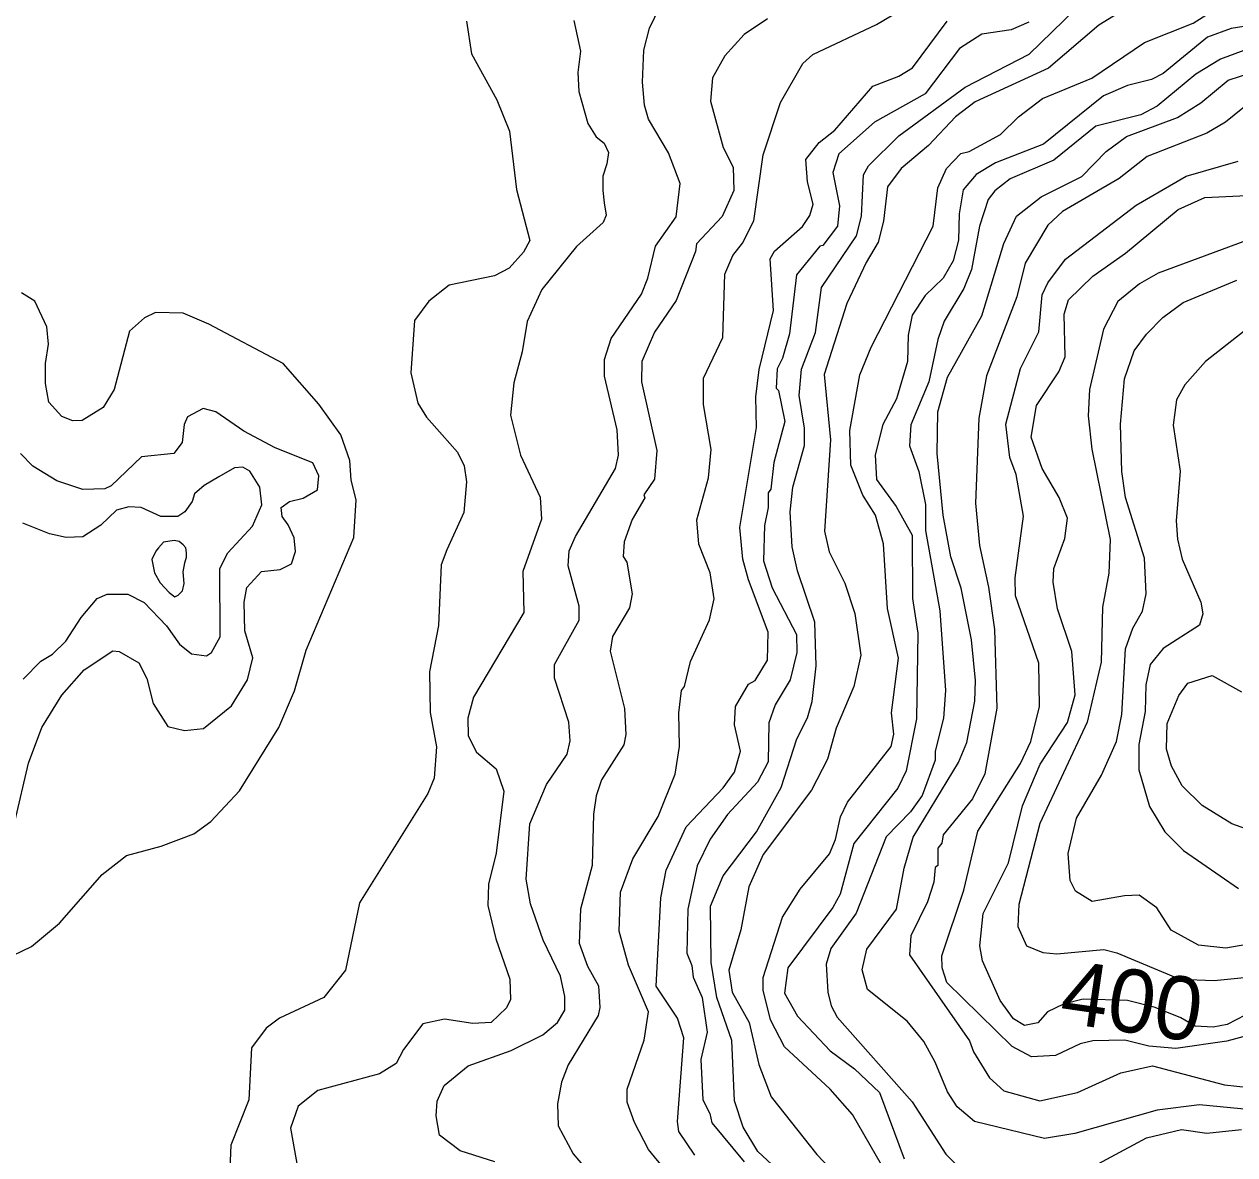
# Model space of a CAD drawing. Extents: x 673.6 to 698.9, y 7012 to 7040.1.
# Drawn here: x 675.042 to 676.578, y 7037.51 to 7038.944 of the extents above; entities that cross this region are included whole.
import ezdxf
from ezdxf.enums import TextEntityAlignment as Align

# ---------------------------------------------------------------- set-up
doc = ezdxf.new("R2010")
doc.units = 0
doc.header["$LTSCALE"] = 0.032
doc.layers.add('1', color=7, linetype='Continuous', lineweight=25)
doc.layers.add('2', color=7, linetype='Continuous', lineweight=13)
doc.layers.add('61', color=7, linetype='Continuous')

msp = doc.modelspace()

# ---------------------------------------------------------------- linework, layer by layer
at = {"layer": '1'}
for points in [[(675.6031, 7038.9478), (675.6096, 7038.9062), (675.6418, 7038.848), (675.6579, 7038.8082), (675.6666, 7038.7342), (675.6836, 7038.6694), (675.6755, 7038.6545), (675.6571, 7038.6346), (675.6388, 7038.6248), (675.581, 7038.6129), (675.5554, 7038.5927), (675.5373, 7038.5678), (675.5324, 7038.5016), (675.5413, 7038.463), (675.5525, 7038.4452), (675.5721, 7038.4231), (675.5917, 7038.401), (675.6003, 7038.3836), (675.603, 7038.3635), (675.5999, 7038.3245), (675.578, 7038.2772), (675.5709, 7038.2579), (675.5676, 7038.181), (675.5562, 7038.1223), (675.5569, 7038.0706), (675.5652, 7038.027), (675.5619, 7037.9875), (675.5539, 7037.9678), (675.4675, 7037.8293), (675.4496, 7037.744), (675.4219, 7037.7093), (675.366, 7037.6828), (675.3488, 7037.6704), (675.3304, 7037.6455), (675.3269, 7037.5795), (675.3039, 7037.522), (675.3023, 7037.4821)], [(675.8563, 7037.8708), (675.882, 7037.9256), (675.9287, 7037.9751), (675.9433, 7037.9949), (675.9506, 7038.0217), (675.9432, 7038.0549), (675.9443, 7038.0785), (675.961, 7038.1067), (675.9695, 7038.1112), (675.9851, 7038.1371), (675.9859, 7038.1728), (675.9609, 7038.2389), (675.9539, 7038.2653), (675.9498, 7038.3052), (675.9711, 7038.4321), (675.9704, 7038.4712), (675.9743, 7038.5057), (675.9925, 7038.5805), (675.9883, 7038.6463), (675.994, 7038.6559), (676.0295, 7038.6873), (676.0388, 7038.7012), (676.0432, 7038.7156), (676.0359, 7038.7439), (676.0339, 7038.7721), (676.0506, 7038.7938), (676.0703, 7038.8095), (676.1188, 7038.8654), (676.1516, 7038.8778), (676.1691, 7038.8886), (676.2131, 7038.9479)], [(676.6055, 7038.9436), (676.5735, 7038.9385), (676.5434, 7038.9274), (676.4872, 7038.8812), (676.4725, 7038.8736), (676.442, 7038.8662), (676.4116, 7038.8532), (676.3351, 7038.7917), (676.2743, 7038.7682), (676.25, 7038.7533), (676.2333, 7038.7337), (676.2283, 7038.7034), (676.2274, 7038.67), (676.2208, 7038.6438), (676.208, 7038.6219), (676.1851, 7038.5996), (676.1685, 7038.5746), (676.1635, 7038.5496), (676.1625, 7038.516), (676.1486, 7038.4688), (676.1315, 7038.4361), (676.1215, 7038.3977), (676.1234, 7038.3664), (676.1484, 7038.3321), (676.1685, 7038.2955), (676.1692, 7038.2152), (676.1758, 7038.1712), (676.1741, 7038.0628), (676.1609, 7037.9967), (676.1506, 7037.9748), (676.0946, 7037.9044), (676.0774, 7037.8401), (676.0681, 7037.8233), (676.0109, 7037.7468), (676.0066, 7037.7147), (676.0232, 7037.6855), (676.0646, 7037.6414), (676.0955, 7037.6187), (676.1271, 7037.5885), (676.1584, 7037.5043)], [(676.6139, 7037.6987), (676.5685, 7037.6751), (676.5506, 7037.6717), (676.5276, 7037.6728), (676.5094, 7037.6833), (676.4771, 7037.6965), (676.442, 7037.7054), (676.3857, 7037.7072), (676.3607, 7037.7008), (676.3402, 7037.6912), (676.328, 7037.6769), (676.3112, 7037.6735), (676.297, 7037.682), (676.2805, 7037.7052), (676.2577, 7037.7556), (676.2547, 7037.7748), (676.2588, 7037.8159), (676.2907, 7037.88), (676.3086, 7037.9524), (676.3311, 7038.0052), (676.3658, 7038.0582), (676.3753, 7038.0931), (676.3714, 7038.1479), (676.3532, 7038.2024), (676.3476, 7038.2361), (676.3483, 7038.2534), (676.3624, 7038.2916), (676.3656, 7038.3171), (676.3551, 7038.3434), (676.3334, 7038.3803), (676.3196, 7038.4202), (676.3265, 7038.4602), (676.3547, 7038.5028), (676.3628, 7038.5221), (676.3615, 7038.5759), (676.3671, 7038.5943), (676.3977, 7038.6242), (676.4395, 7038.6535), (676.5061, 7038.709), (676.5401, 7038.7242), (676.6463, 7038.7291)], [(675.0282, 7037.7629), (675.0511, 7037.7737), (675.0866, 7037.8034), (675.141, 7037.8652), (675.1716, 7037.8893), (675.2155, 7037.901), (675.2571, 7037.9169), (675.2787, 7037.9323), (675.3152, 7037.9712), (675.3649, 7038.0516), (675.3849, 7038.098), (675.3996, 7038.1496), (675.46, 7038.2929), (675.4633, 7038.3405), (675.4567, 7038.3655), (675.455, 7038.3902), (675.4436, 7038.4231), (675.4159, 7038.4618), (675.3706, 7038.5136), (675.2763, 7038.5634), (675.2438, 7038.5772), (675.2085, 7038.578), (675.1947, 7038.5716), (675.1757, 7038.5545), (675.1559, 7038.4803), (675.1422, 7038.4576), (675.1153, 7038.441), (675.1037, 7038.4408), (675.0896, 7038.4463), (675.073, 7038.4642), (675.0689, 7038.488), (675.0689, 7038.5134), (675.0729, 7038.5381), (675.0706, 7038.5598), (675.0556, 7038.5927), (675.0384, 7038.6033)], [(675.871, 7037.552), (675.8791, 7037.658), (675.8708, 7037.6831), (675.8438, 7037.7235), (675.8497, 7037.8358), (675.8563, 7037.8708)], [(675.8929, 7037.5092), (675.8724, 7037.5392), (675.871, 7037.552)]]:
    msp.add_lwpolyline(points, dxfattribs=at)
at = {"layer": '2'}
for points in [[(675.9038, 7038.4614), (675.9038, 7038.4947), (675.9284, 7038.5463), (675.9309, 7038.6267), (675.9412, 7038.6505), (675.9532, 7038.6662), (675.9678, 7038.6943), (675.9796, 7038.7783), (676.0015, 7038.8446), (676.03, 7038.894), (676.0425, 7038.9054), (676.1235, 7038.9433), (676.1554, 7038.9627), (676.1834, 7038.9874), (676.2196, 7039.0277), (676.2547, 7039.0511), (676.2916, 7039.0808), (676.3678, 7039.1652), (676.4349, 7039.2174), (676.5299, 7039.2798), (676.5444, 7039.2961), (676.5523, 7039.33), (676.5579, 7039.4265), (676.581, 7039.4883)], [(676.2123, 7038.7607), (676.2304, 7038.7797), (676.2408, 7038.7822), (676.2808, 7038.804), (676.3034, 7038.8264), (676.3342, 7038.8498), (676.3965, 7038.8753), (676.4633, 7038.9206), (676.525, 7038.9454), (676.5585, 7038.9663), (676.6134, 7039.0256)], [(676.5151, 7039.0105), (676.4053, 7038.9425), (676.3416, 7038.8882), (676.2486, 7038.8456), (676.2237, 7038.8264), (676.1892, 7038.7902), (676.1547, 7038.7607), (676.1374, 7038.7376), (676.1323, 7038.6942), (676.1255, 7038.6672), (676.1102, 7038.6417), (676.0859, 7038.5896), (676.057, 7038.4995), (676.0649, 7038.4167), (676.0575, 7038.3007), (676.0634, 7038.2744), (676.0832, 7038.2346), (676.0959, 7038.1962), (676.1033, 7038.1433), (676.0944, 7038.1038), (676.0721, 7038.0509), (676.0614, 7038.0115), (676.0408, 7037.972), (675.9797, 7037.8905), (675.9615, 7037.8494), (675.9511, 7037.7952), (675.9359, 7037.744), (675.9403, 7037.7159), (675.9616, 7037.6774), (675.974, 7037.6242), (675.9896, 7037.5832), (676.0477, 7037.51), (676.1094, 7037.4453)], [(675.8332, 7038.6218), (675.8428, 7038.6623), (675.869, 7038.6997), (675.8742, 7038.742), (675.8594, 7038.7806), (675.8339, 7038.8236), (675.8291, 7038.8411), (675.8265, 7038.8705), (675.8282, 7038.9108), (675.8353, 7038.9387), (675.8561, 7038.982)], [(676.0079, 7037.4812), (675.9729, 7037.514), (675.954, 7037.5447), (675.9432, 7037.5779), (675.94, 7037.6548), (675.9207, 7037.7091), (675.9137, 7037.7534), (675.9129, 7037.8249), (675.929, 7037.8637), (675.9713, 7037.9193), (676.0024, 7037.9756), (676.0223, 7038.0375), (676.0359, 7038.0641), (676.0419, 7038.0845), (676.0467, 7038.1298), (676.0452, 7038.1852), (676.0233, 7038.2505), (676.0164, 7038.281), (676.014, 7038.3252), (676.0171, 7038.3566), (676.0319, 7038.4096), (676.0319, 7038.4313), (676.0254, 7038.4729), (676.0283, 7038.5062), (676.0459, 7038.5526), (676.0537, 7038.6097), (676.0978, 7038.6753), (676.1043, 7038.7005), (676.1067, 7038.7527), (676.1132, 7038.7644), (676.1519, 7038.8022), (676.2357, 7038.8639), (676.317, 7038.9057), (676.3757, 7038.9628)], [(675.7395, 7038.9487), (675.7476, 7038.9095), (675.7444, 7038.8828), (675.7456, 7038.8586), (675.7572, 7038.8179), (675.7676, 7038.8012), (675.778, 7038.7928), (675.7833, 7038.7813), (675.7812, 7038.7666), (675.776, 7038.7509), (675.776, 7038.7331), (675.778, 7038.7174), (675.7805, 7038.7016), (675.7766, 7038.6925), (675.7426, 7038.6617), (675.6988, 7038.6074), (675.68, 7038.5666), (675.6738, 7038.5282), (675.663, 7038.4888), (675.659, 7038.4481), (675.6718, 7038.3971), (675.6967, 7038.3437), (675.6983, 7038.3159), (675.6745, 7038.2498), (675.676, 7038.1977), (675.6119, 7038.0903), (675.6047, 7038.0635), (675.6051, 7038.0413), (675.6159, 7038.0202), (675.6406, 7037.9992), (675.6506, 7037.9708), (675.6409, 7037.8922), (675.6311, 7037.8531), (675.6302, 7037.8257), (675.6403, 7037.7837), (675.658, 7037.7324), (675.6589, 7037.7065), (675.654, 7037.696), (675.6346, 7037.6773), (675.611, 7037.6764), (675.5752, 7037.6815), (675.5476, 7037.6756), (675.5233, 7037.6433), (675.514, 7037.6256), (675.4926, 7037.6123), (675.4144, 7037.5912), (675.3894, 7037.5714), (675.3796, 7037.5434), (675.3892, 7037.4912)], [(675.9852, 7038.9507), (675.9553, 7038.931), (675.9311, 7038.9036), (675.9153, 7038.8758), (675.9129, 7038.8461), (675.9286, 7038.7873), (675.9414, 7038.7626), (675.9424, 7038.7328), (675.9275, 7038.7), (675.895, 7038.6653), (675.8938, 7038.6556), (675.869, 7038.5932), (675.8417, 7038.5532), (675.8257, 7038.516), (675.825, 7038.4901), (675.8446, 7038.4032)], [(676.3167, 7038.9463), (676.2942, 7038.9369), (676.2569, 7038.9314), (676.2287, 7038.9132), (676.1853, 7038.8555), (676.121, 7038.8197), (676.0755, 7038.7793), (676.0681, 7038.7559), (676.0763, 7038.7135), (676.0738, 7038.6877), (676.0553, 7038.6631), (676.0513, 7038.6622), (676.022, 7038.6261), (676.0128, 7038.5513), (676.0043, 7038.5203), (675.9973, 7038.5068), (675.9959, 7038.4821), (675.9991, 7038.479), (676.0072, 7038.44), (675.9933, 7038.3878), (675.9892, 7038.354), (675.986, 7038.3492), (675.9859, 7038.3307), (675.9811, 7038.308), (675.9802, 7038.2632), (675.9908, 7038.2287), (676.0219, 7038.1698), (676.0222, 7038.1469), (676.0139, 7038.1121), (675.9949, 7038.0805), (675.9867, 7038.0575), (675.9859, 7038.008), (675.9722, 7037.9825), (675.9344, 7037.9413), (675.9122, 7037.9102), (675.8958, 7037.876), (675.8841, 7037.8211), (675.8825, 7037.7656), (675.8891, 7037.7497), (675.8907, 7037.735), (675.9021, 7037.7091), (675.9087, 7037.6651), (675.9006, 7037.6305), (675.903, 7037.5792), (675.912, 7037.5619), (675.9144, 7037.5503), (675.9553, 7037.5009)], [(676.6451, 7038.9314), (676.56, 7038.8995), (676.5285, 7038.8803), (676.4796, 7038.8397), (676.4587, 7038.829), (676.4015, 7038.8144), (676.3482, 7038.7714), (676.2931, 7038.7478), (676.2737, 7038.7325), (676.2651, 7038.7217), (676.2539, 7038.6876), (676.2438, 7038.6327), (676.2343, 7038.6088), (676.2093, 7038.567), (676.2012, 7038.544), (676.1897, 7038.49), (676.1668, 7038.4358), (676.1652, 7038.409), (676.177, 7038.3766), (676.1855, 7038.3347), (676.1856, 7038.3014), (676.2036, 7038.1999), (676.2111, 7038.0986), (676.2085, 7038.0637), (676.198, 7038.0216), (676.1979, 7038.0102), (676.1813, 7037.9654), (676.1664, 7037.9449), (676.1357, 7037.9132), (676.0977, 7037.8162), (676.0655, 7037.7715), (676.0594, 7037.7516), (676.0616, 7037.716), (676.0658, 7037.6987), (676.0735, 7037.6841), (676.1686, 7037.5769), (676.2114, 7037.5103), (676.2265, 7037.4951)], [(676.6121, 7037.5655), (676.5332, 7037.5729), (676.4793, 7037.5661), (676.3751, 7037.5368), (676.3364, 7037.5303), (676.2479, 7037.5518), (676.2259, 7037.5706), (676.2134, 7037.5897), (676.1979, 7037.6272), (676.1833, 7037.6532), (676.1624, 7037.6792), (676.1118, 7037.7193), (676.1051, 7037.7444), (676.1109, 7037.7707), (676.1486, 7037.8212), (676.1585, 7037.8734), (676.1698, 7037.9124), (676.2276, 7038.0072), (676.2378, 7038.0328), (676.2481, 7038.0849), (676.2489, 7038.1112), (676.2439, 7038.163), (676.2308, 7038.2284), (676.2177, 7038.2682), (676.2078, 7038.3211), (676.2005, 7038.3993), (676.2013, 7038.4522), (676.2133, 7038.4963), (676.2571, 7038.5739), (676.2849, 7038.6656), (676.301, 7038.7005), (676.3324, 7038.7248), (676.384, 7038.7508), (676.415, 7038.7826), (676.4407, 7038.8013), (676.5055, 7038.8254), (676.5349, 7038.8441), (676.5698, 7038.8731), (676.648, 7038.8983)], [(676.6082, 7038.8536), (676.5661, 7038.8194), (676.5425, 7038.8058), (676.4669, 7038.7762), (676.4313, 7038.748), (676.3593, 7038.7063), (676.3409, 7038.6888), (676.3121, 7038.6408), (676.3014, 7038.5982), (676.2631, 7038.4977), (676.2531, 7038.444), (676.249, 7038.3361), (676.2539, 7038.2826), (676.2654, 7038.2296), (676.2729, 7038.1762), (676.2761, 7038.0763), (676.2609, 7037.9931), (676.245, 7037.9611), (676.208, 7037.9155), (676.2063, 7037.9049), (676.2013, 7037.8986), (676.2012, 7037.8768), (676.198, 7037.8743), (676.1962, 7037.8553), (676.188, 7037.8307), (676.167, 7037.7873), (676.1652, 7037.7631), (676.2415, 7037.6543), (676.2464, 7037.6404), (676.2666, 7037.6072), (676.2851, 7037.5907), (676.3308, 7037.578), (676.3783, 7037.5885), (676.4336, 7037.6136), (676.4735, 7037.6223), (676.5648, 7037.5984), (676.5962, 7037.5952)], [(676.5944, 7037.6608), (676.5677, 7037.6538), (676.5031, 7037.6445), (676.469, 7037.6474), (676.4386, 7037.6551), (676.3978, 7037.6543), (676.382, 7037.6502), (676.3505, 7037.6354), (676.3199, 7037.6338), (676.2955, 7037.6472), (676.2128, 7037.7283), (676.2068, 7037.7466), (676.2062, 7037.7619), (676.234, 7037.8455), (676.2518, 7037.9203), (676.3061, 7038.0062), (676.319, 7038.0338), (676.3301, 7038.0785), (676.3295, 7038.1331), (676.2999, 7038.2189), (676.2994, 7038.2414), (676.3097, 7038.3198), (676.3006, 7038.3725), (676.2925, 7038.3944), (676.2875, 7038.4363), (676.306, 7038.507), (676.3293, 7038.5538), (676.3336, 7038.6004), (676.3406, 7038.616), (676.363, 7038.646), (676.4527, 7038.7143), (676.5165, 7038.7512), (676.5822, 7038.7702)], [(676.0896, 7038.4283), (676.1021, 7038.4989), (676.1165, 7038.5341), (676.1952, 7038.6876), (676.2013, 7038.7364), (676.2123, 7038.7607)], [(676.6433, 7038.6881), (676.4806, 7038.6281), (676.457, 7038.6145), (676.4297, 7038.5919), (676.4115, 7038.5571), (676.3936, 7038.4806), (676.392, 7038.447), (676.3965, 7038.4048), (676.4199, 7038.29), (676.4183, 7038.2476), (676.41, 7038.2044), (676.4083, 7038.1347), (676.3905, 7038.0586), (676.3305, 7037.9297), (676.3038, 7037.827), (676.3027, 7037.7992), (676.3135, 7037.7748), (676.3345, 7037.7662), (676.3521, 7037.7645), (676.4117, 7037.7702), (676.4283, 7037.7659), (676.5083, 7037.7324), (676.5519, 7037.7308), (676.6492, 7037.7406)], [(675.7943, 7038.4295), (675.7782, 7038.4976), (675.7782, 7038.5186), (675.7866, 7038.545), (675.825, 7038.6013), (675.8332, 7038.6218)], [(676.6102, 7037.7792), (676.5668, 7037.7719), (676.532, 7037.7755), (676.4973, 7037.7948), (676.479, 7037.8228), (676.4567, 7037.8391), (676.4379, 7037.8383), (676.3969, 7037.8311), (676.3758, 7037.844), (676.369, 7037.8576), (676.3665, 7037.8918), (676.3773, 7037.9365), (676.4087, 7037.9911), (676.4278, 7038.0341), (676.4347, 7038.0683), (676.4392, 7038.1513), (676.4486, 7038.1776), (676.4609, 7038.1992), (676.4657, 7038.2214), (676.4633, 7038.2665), (676.4393, 7038.3433), (676.4347, 7038.3763), (676.433, 7038.4363), (676.4379, 7038.4942), (676.4503, 7038.5295), (676.4658, 7038.5508), (676.4866, 7038.5717), (676.5127, 7038.591), (676.5804, 7038.6191)], [(676.6234, 7038.5809), (676.5409, 7038.5158), (676.5145, 7038.4864), (676.5039, 7038.4675)], [(675.9122, 7038.2478), (675.8981, 7038.2843), (675.8955, 7038.3153), (675.9103, 7038.3685), (675.9136, 7038.4043), (675.9038, 7038.4614)], [(676.5039, 7038.4675), (676.4996, 7038.4354), (676.5085, 7038.377), (676.5037, 7038.3138), (676.5051, 7038.2907), (676.5114, 7038.2653)], [(675.03, 7037.9322), (675.0475, 7038.0065), (675.0643, 7038.0517), (675.0896, 7038.0929), (675.1179, 7038.1249), (675.1545, 7038.149), (675.1626, 7038.1482), (675.1875, 7038.1339), (675.1977, 7038.114), (675.2054, 7038.082), (675.2241, 7038.0531), (675.2453, 7038.048), (675.2695, 7038.0505), (675.3051, 7038.0793), (675.3254, 7038.1123), (675.3318, 7038.14), (675.322, 7038.1745), (675.3212, 7038.2106), (675.3245, 7038.2291), (675.3431, 7038.2497), (675.3669, 7038.2522), (675.381, 7038.2595), (675.386, 7038.2748), (675.3843, 7038.2924), (675.3768, 7038.3088), (675.3694, 7038.3193), (675.3681, 7038.3308), (675.3785, 7038.3382), (675.3957, 7038.3427), (675.4139, 7038.353), (675.4156, 7038.3708), (675.408, 7038.3873), (675.3604, 7038.4064), (675.3206, 7038.4276), (675.285, 7038.4522), (675.2689, 7038.4563), (675.249, 7038.4458), (675.2449, 7038.4361), (675.2424, 7038.4133), (675.2319, 7038.3991), (675.1908, 7038.3952), (675.1521, 7038.3582), (675.1443, 7038.3545), (675.1162, 7038.3537), (675.0833, 7038.3645), (675.053, 7038.3831), (675.0374, 7038.3991)], [(675.6389, 7037.5007), (675.5951, 7037.5145), (675.5688, 7037.5344), (675.5645, 7037.5592), (675.566, 7037.5776), (675.575, 7037.5975), (675.6053, 7037.6225), (675.66, 7037.6421), (675.7, 7037.6618), (675.7188, 7037.6773), (675.7279, 7037.6931), (675.728, 7037.7103), (675.7223, 7037.7364), (675.7006, 7037.782), (675.6844, 7037.8281), (675.6787, 7037.8595), (675.6836, 7037.9296), (675.7048, 7037.9794), (675.7308, 7038.0177), (675.7345, 7038.0349), (675.7331, 7038.0584), (675.7147, 7038.1142), (675.715, 7038.1317), (675.746, 7038.1877), (675.746, 7038.2057), (675.7321, 7038.2567), (675.7336, 7038.2757), (675.7416, 7038.2938), (675.7921, 7038.3803), (675.7962, 7038.397), (675.7943, 7038.4295)], [(676.1299, 7037.4967), (676.0929, 7037.5608), (676.0646, 7037.593), (676.0068, 7037.6467), (675.989, 7037.681), (675.9795, 7037.7185), (675.9794, 7037.7345), (676.0039, 7037.811), (676.0266, 7037.8468), (676.0637, 7037.8916), (676.0713, 7037.9096), (676.0776, 7037.9383), (676.0867, 7037.9569), (676.142, 7038.0278), (676.1453, 7038.0431), (676.1422, 7038.0704), (676.1511, 7038.1396), (676.1372, 7038.2025), (676.1324, 7038.2845), (676.1221, 7038.321), (676.106, 7038.3463), (676.091, 7038.3844), (676.0896, 7038.4283)], [(675.8446, 7038.4032), (675.8416, 7038.3666), (675.8282, 7038.3468), (675.8295, 7038.343), (675.8132, 7038.3155), (675.803, 7038.2871)], [(675.0405, 7038.113), (675.063, 7038.1358), (675.0777, 7038.1446), (675.0949, 7038.1611), (675.1143, 7038.1912), (675.1345, 7038.2153), (675.1473, 7038.2207), (675.1733, 7038.2209), (675.1942, 7038.2101), (675.2223, 7038.1805), (675.239, 7038.1573), (675.2541, 7038.1451), (675.2734, 7038.1425), (675.2795, 7038.1468), (675.2907, 7038.1666), (675.2901, 7038.2533), (675.3003, 7038.2734), (675.3316, 7038.3072), (675.3433, 7038.334), (675.3409, 7038.3566), (675.3281, 7038.377), (675.3192, 7038.3821), (675.3087, 7038.3811), (675.2888, 7038.3696), (675.2701, 7038.3589), (675.2581, 7038.3481), (675.2552, 7038.3383), (675.2459, 7038.3253), (675.237, 7038.3192), (675.2152, 7038.3192), (675.1903, 7038.3308), (675.1746, 7038.3318), (675.1589, 7038.3276), (675.1392, 7038.3082), (675.1161, 7038.2937), (675.0951, 7038.2929), (675.074, 7038.2973), (675.0402, 7038.311)], [(675.803, 7038.2871), (675.8019, 7038.2685), (675.8067, 7038.2615), (675.8132, 7038.2214), (675.8101, 7038.2036), (675.7885, 7038.1672), (675.7855, 7038.1486), (675.8036, 7038.0756), (675.8051, 7038.0427), (675.8029, 7038.0298), (675.7746, 7037.9852), (675.7675, 7037.9649), (675.7641, 7037.9419), (675.7624, 7037.8767), (675.7477, 7037.8211), (675.7462, 7037.7781), (675.7567, 7037.749), (675.7705, 7037.7241), (675.7723, 7037.6966), (675.7701, 7037.6863), (675.7321, 7037.6239), (675.7236, 7037.6018), (675.7184, 7037.5744), (675.7195, 7037.5463), (675.7385, 7037.511), (675.7671, 7037.4772)], [(676.5114, 7038.2653), (676.5348, 7038.2106), (676.5376, 7038.1957), (676.5331, 7038.1817), (676.487, 7038.152), (676.4705, 7038.1316), (676.4651, 7038.1058), (676.4641, 7038.0719), (676.4561, 7038.0302), (676.4561, 7037.9979), (676.4697, 7037.9516), (676.4891, 7037.9195), (676.5129, 7037.8956), (676.5825, 7037.8474)], [(675.8764, 7037.4648), (675.8341, 7037.5165), (675.8163, 7037.5506), (675.8069, 7037.5763), (675.8069, 7037.5927), (675.8286, 7037.6552), (675.834, 7037.6908), (675.8086, 7037.7501), (675.797, 7037.7933), (675.7985, 7037.843), (675.8141, 7037.8849), (675.8462, 7037.9387), (675.8677, 7037.9923), (675.8732, 7038.0275), (675.8726, 7038.0704), (675.8759, 7038.0987), (675.8798, 7038.1038), (675.8875, 7038.1355), (675.9114, 7038.1883), (675.9176, 7038.215), (675.9122, 7038.2478)], [(676.6184, 7037.914), (676.5742, 7037.9293), (676.5366, 7037.9527), (676.5114, 7037.9778), (676.4975, 7038.0025), (676.4913, 7038.0241), (676.4923, 7038.0568), (676.5069, 7038.0923), (676.5186, 7038.1078), (676.5494, 7038.1176), (676.5866, 7038.0971)], [(676.3817, 7037.4857), (676.4658, 7037.5313), (676.5102, 7037.5417), (676.5424, 7037.5369), (676.5865, 7037.5416)]]:
    msp.add_lwpolyline(points, dxfattribs=at)
msp.add_lwpolyline([(675.2322, 7038.2889), (675.2186, 7038.2868), (675.2123, 7038.2795), (675.2091, 7038.2753), (675.2039, 7038.2648), (675.2071, 7038.248), (675.2144, 7038.2354), (675.2259, 7038.2229), (675.2332, 7038.2176), (675.2374, 7038.2197), (675.2427, 7038.225), (675.2448, 7038.2344), (675.2437, 7038.2491), (675.2458, 7038.2606), (675.2479, 7038.2679), (675.2479, 7038.2732), (675.2469, 7038.2795), (675.2437, 7038.2836), (675.2385, 7038.2878)], close=True, dxfattribs=at)

# ---------------------------------------------------------------- texts
at = {"layer": '61'}
msp.add_text('400', height=0.08, rotation=351.76, dxfattribs=at).set_placement((676.442, 7037.6651), align=Align.CENTER)

doc.saveas('drawing.dxf')
